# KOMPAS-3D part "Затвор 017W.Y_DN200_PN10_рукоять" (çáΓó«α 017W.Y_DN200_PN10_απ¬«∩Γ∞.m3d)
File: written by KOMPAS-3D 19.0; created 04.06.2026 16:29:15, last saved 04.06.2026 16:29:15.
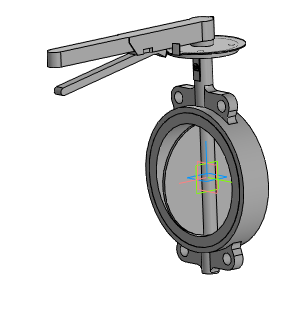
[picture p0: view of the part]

Document properties: Автор: Энергия; Полное имя файла: ..\..\..\3d для проектировщиков\017W разные\x.x Тип 017W.Y(S) Затвор дисковый поворотный межфланцевый\Затвор 017W.Y(S)_DN32-DN350_рукоять\Затвор 017W.Y_DN200_PN10_рукоять.a3d

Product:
- Part/product: Затвор 017W.Y_DN200_PN10_рукоять
    Масса: 18.5149

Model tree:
1. Операция без истории:1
